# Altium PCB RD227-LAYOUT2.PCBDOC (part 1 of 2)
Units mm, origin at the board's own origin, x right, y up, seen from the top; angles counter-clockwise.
Board outline 90 x 40 mm, 4 copper layers (TOP, Mid-Layer 1, Mid-Layer 2, BOTTOM), stack 0.711 mm thick; 157 components, 70 nets, 404 pads, 437 vias.
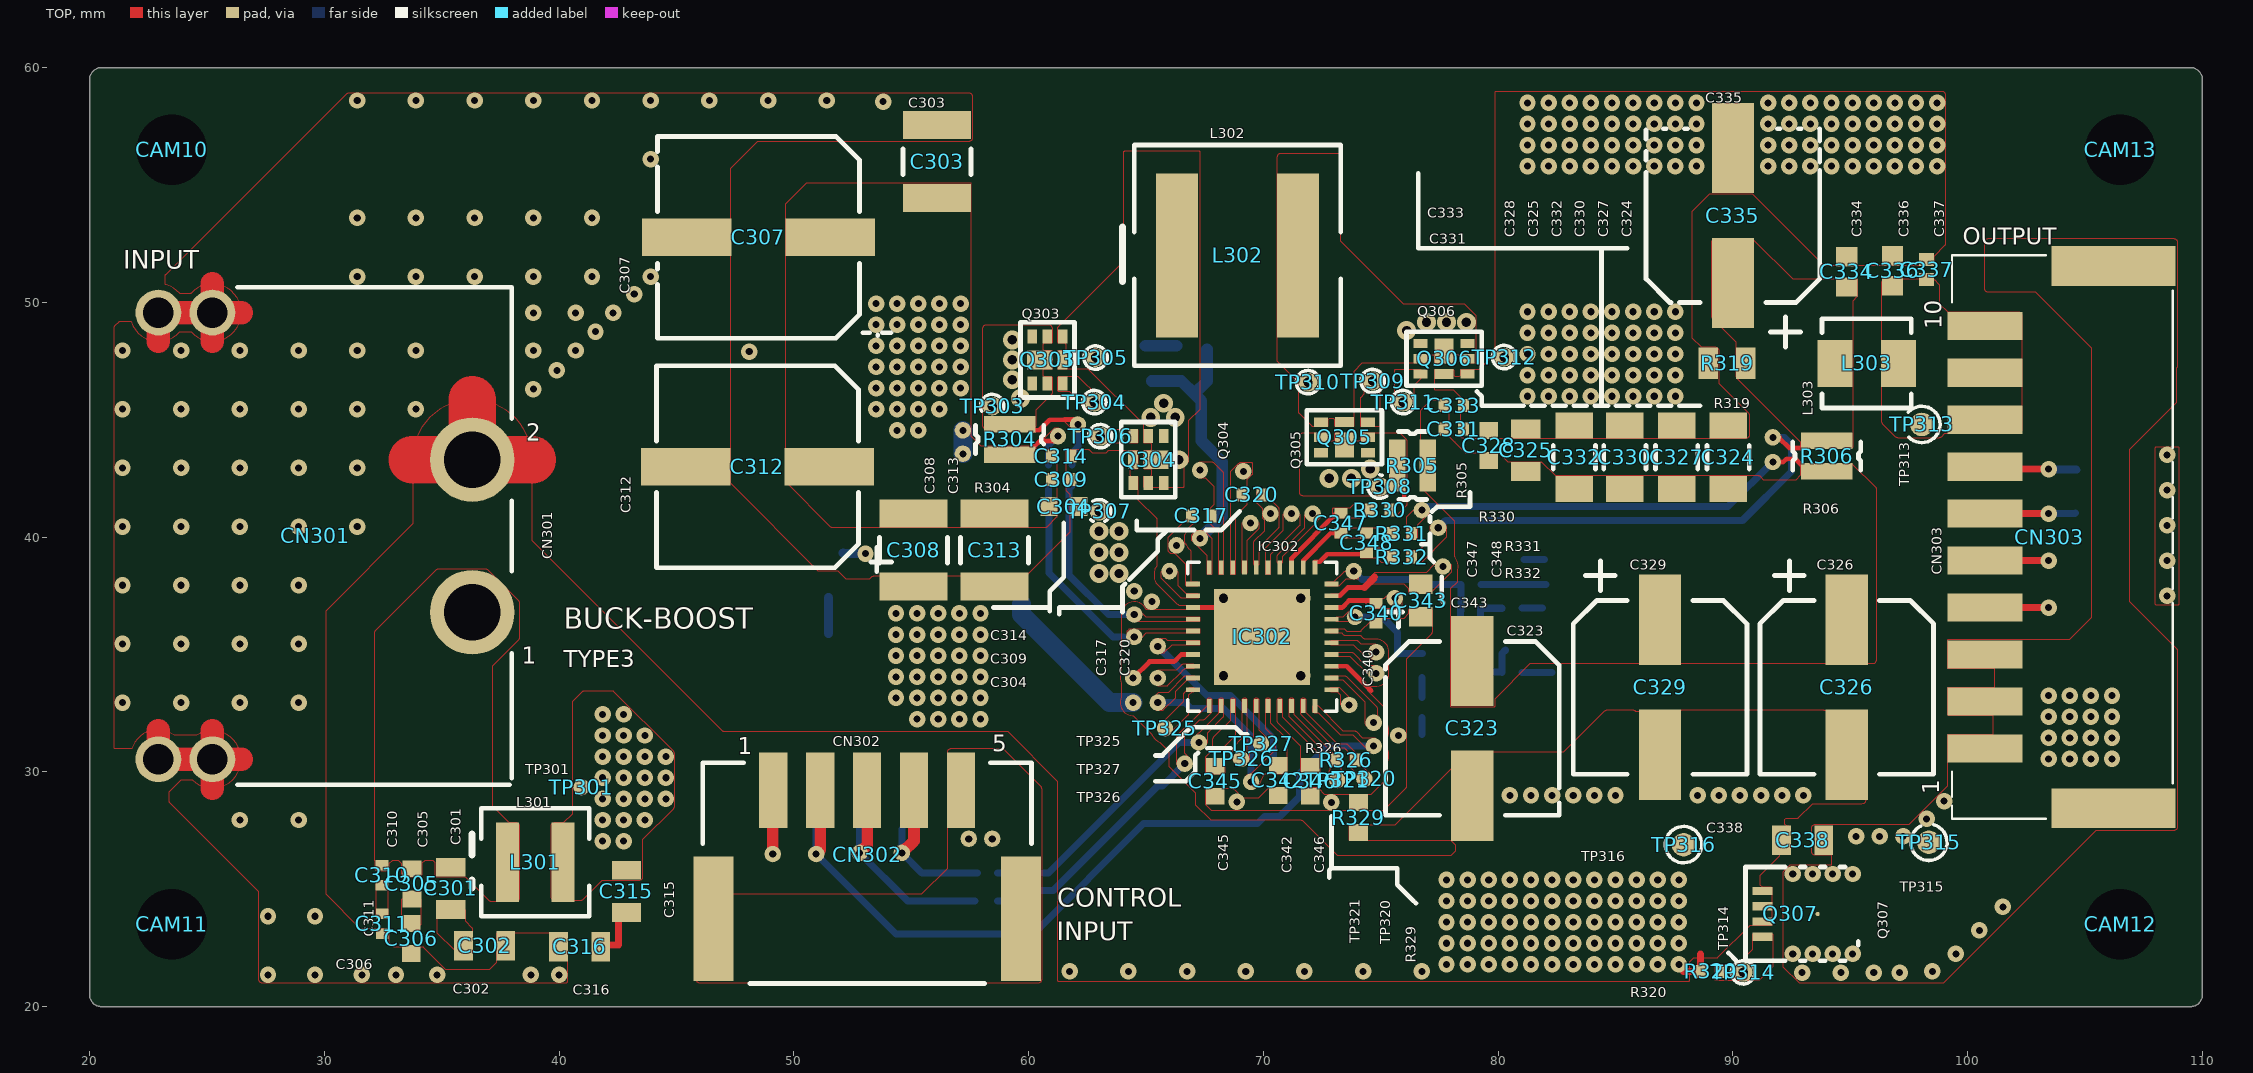
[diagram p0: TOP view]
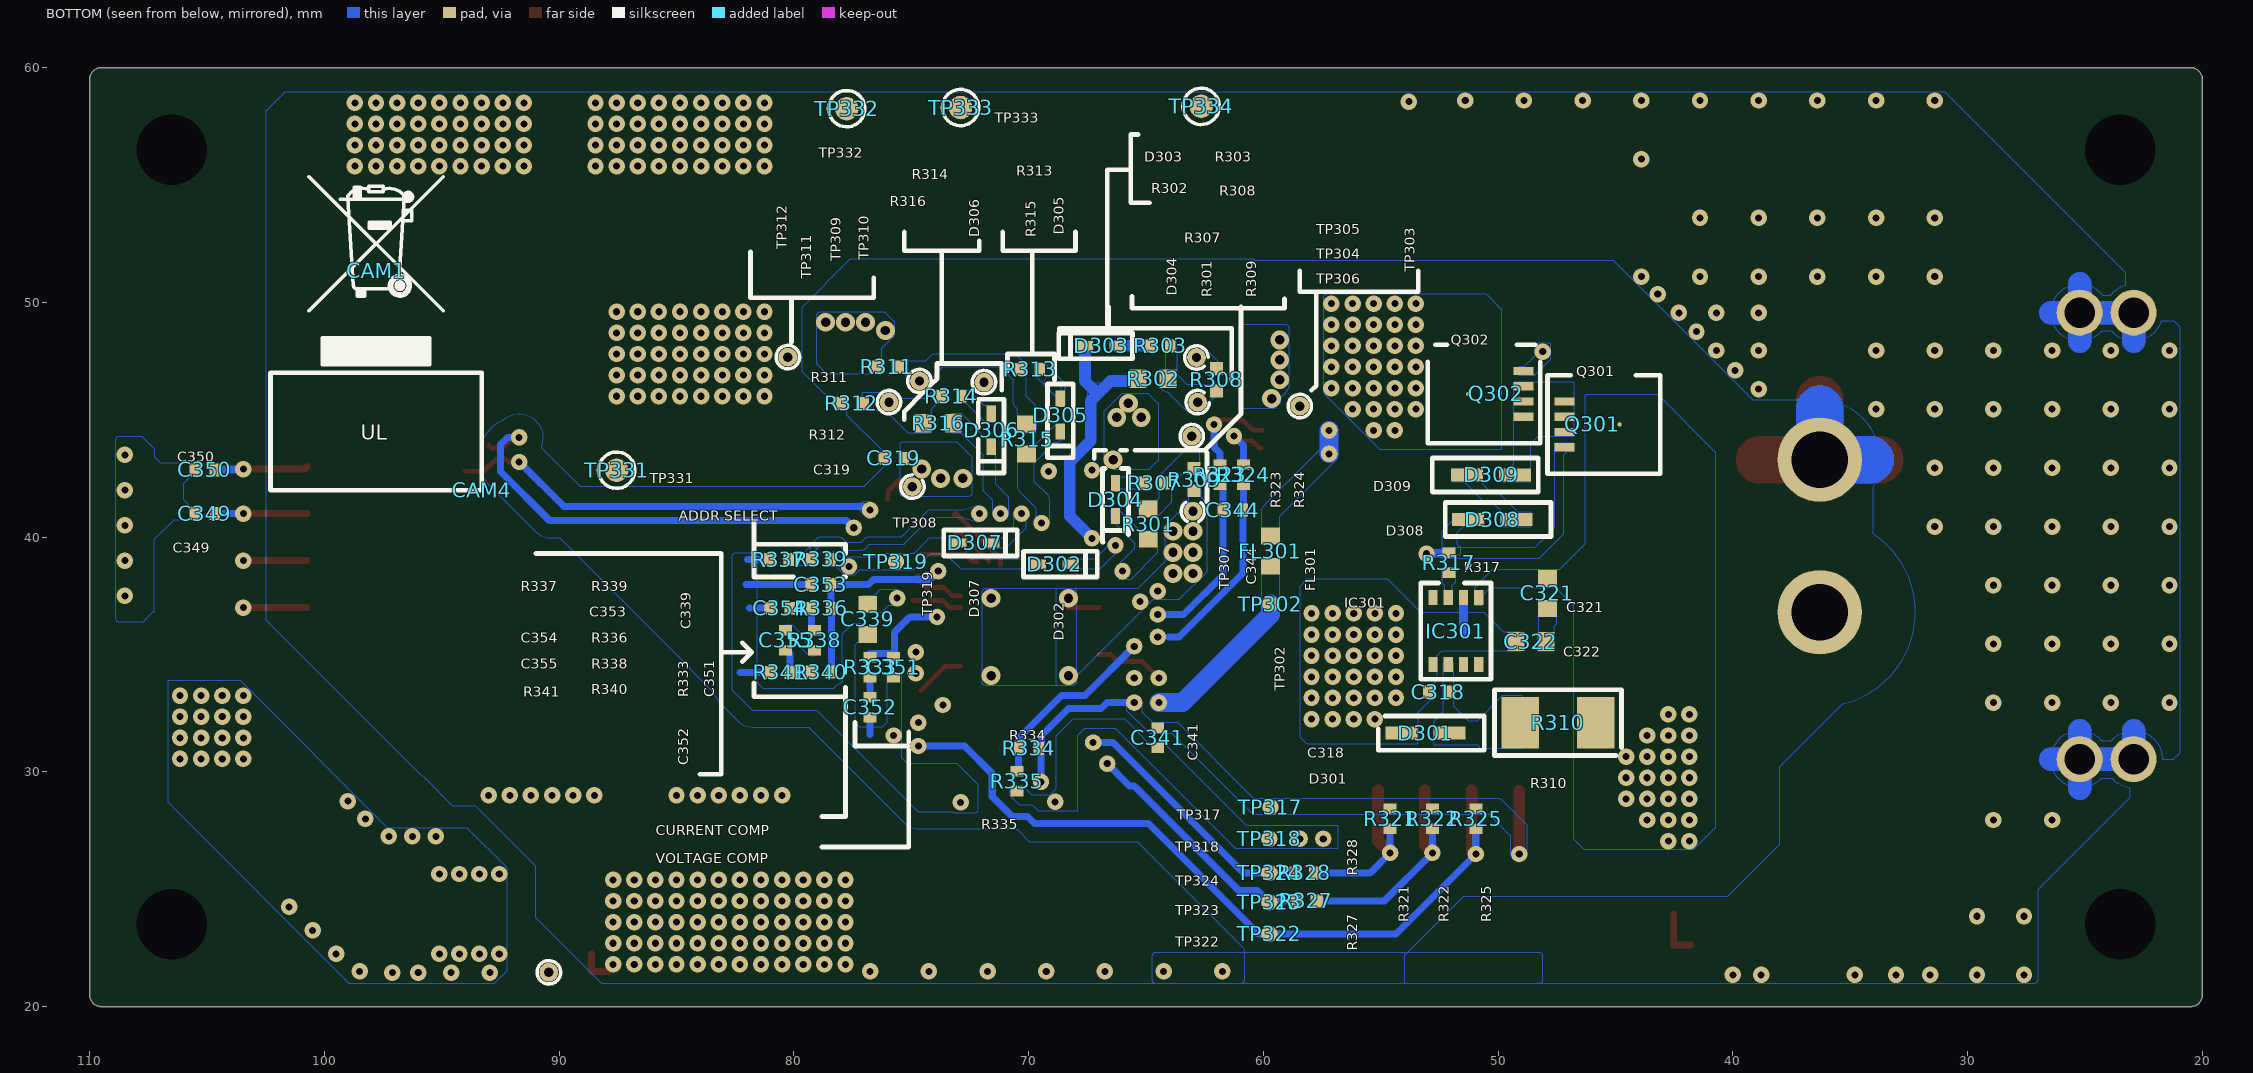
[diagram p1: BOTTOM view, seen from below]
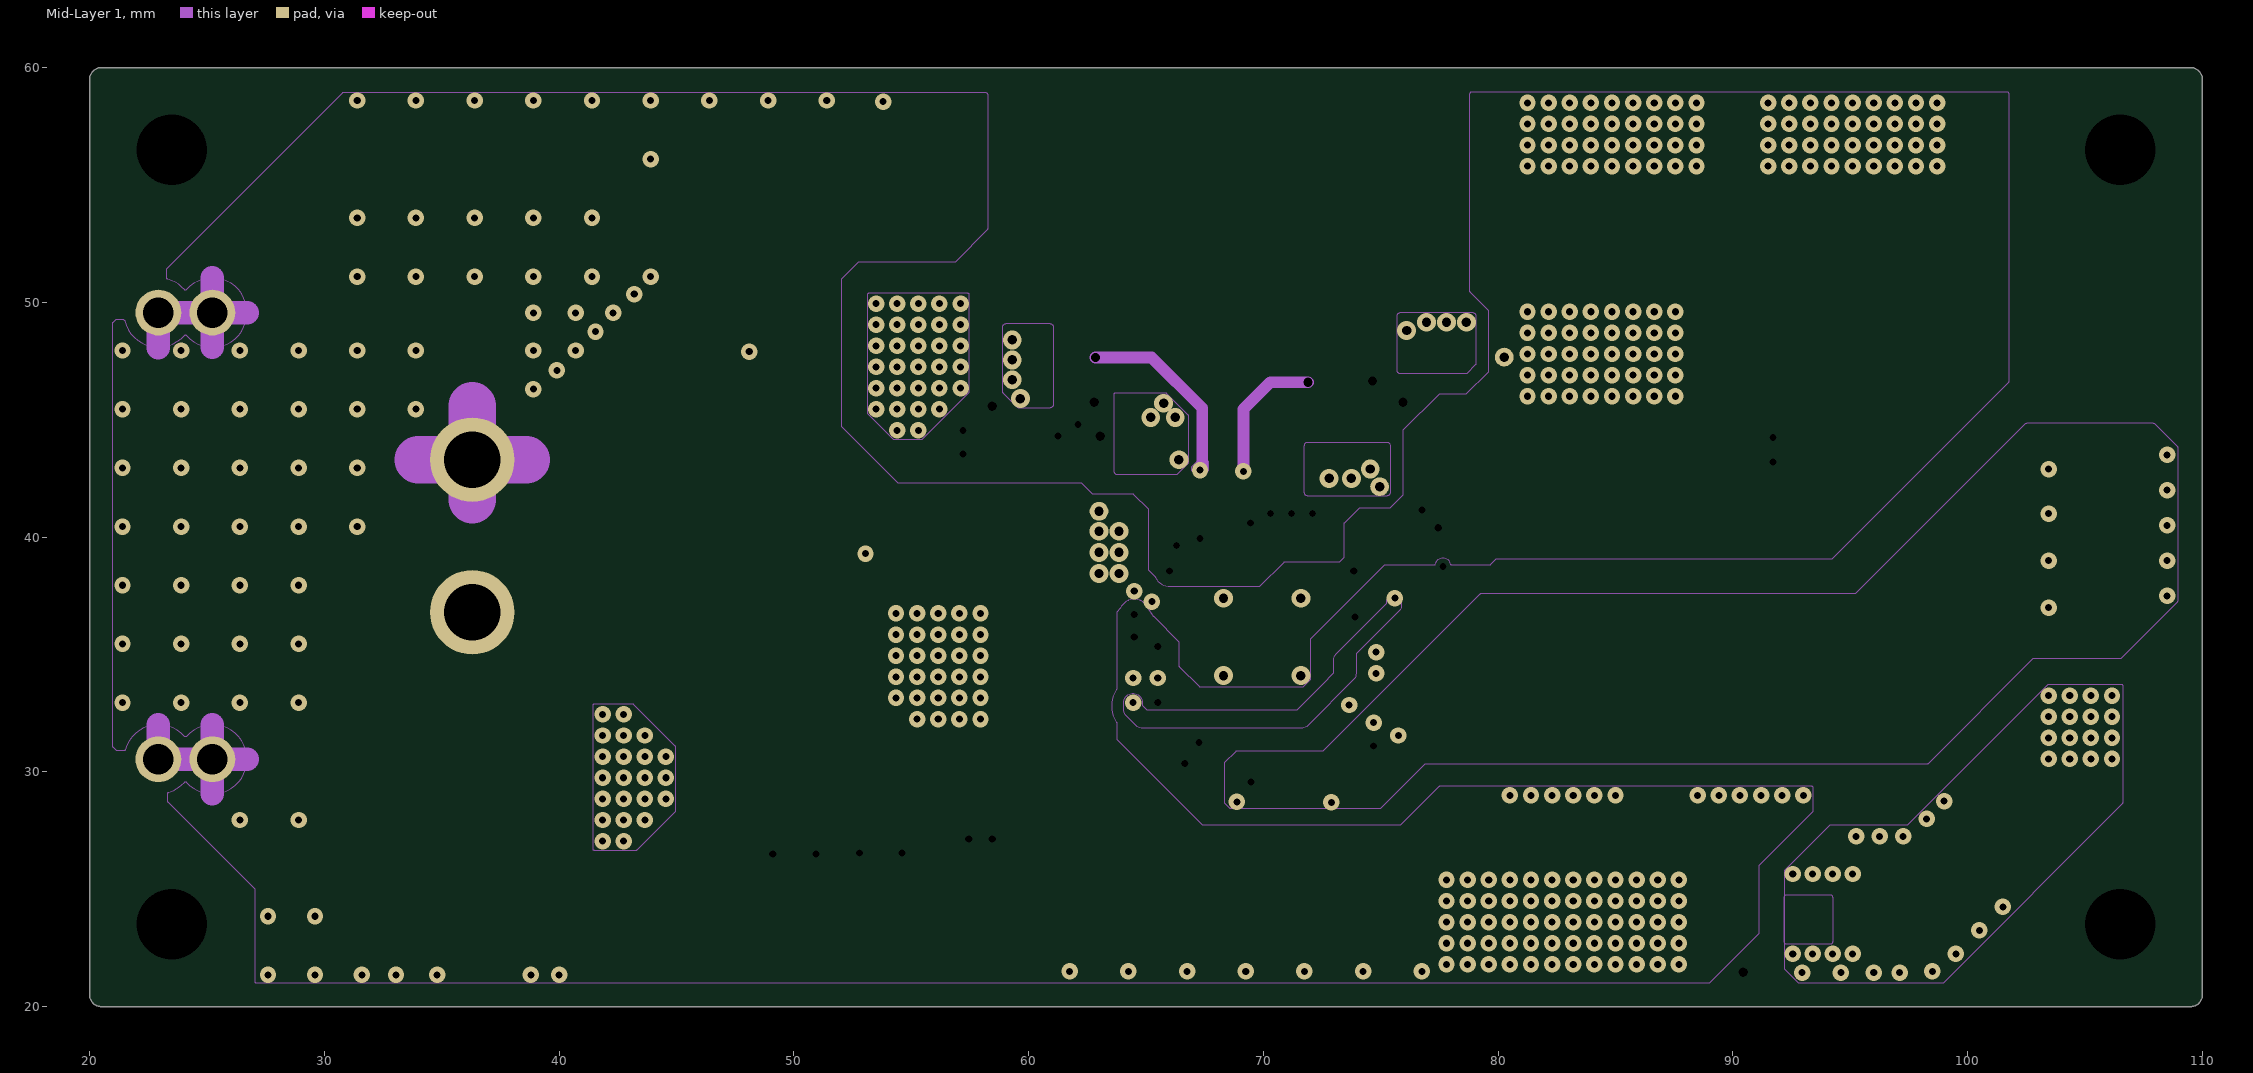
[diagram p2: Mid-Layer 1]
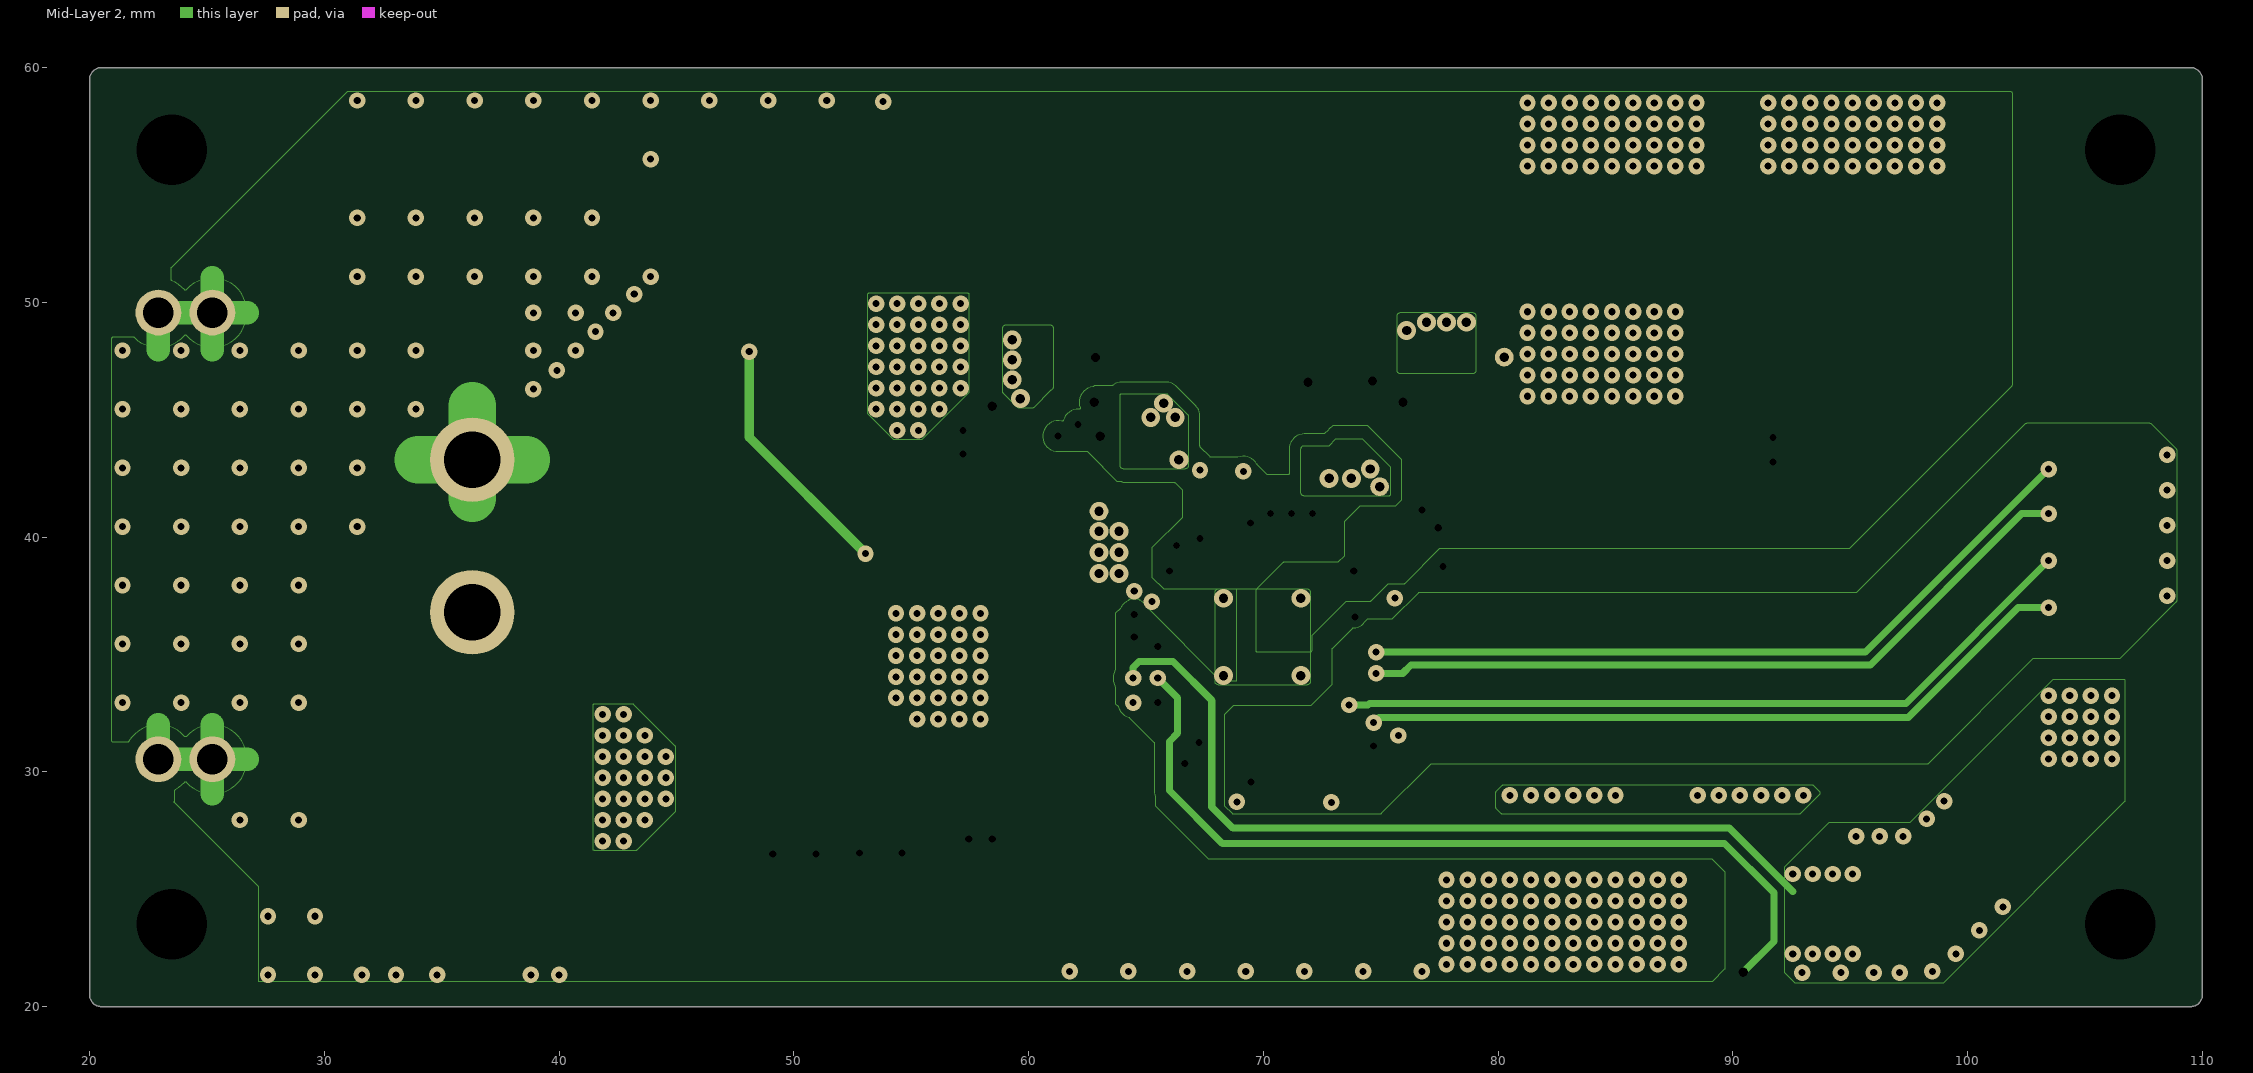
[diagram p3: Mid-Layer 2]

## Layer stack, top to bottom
Top Solder: solder mask 0.0102, Solder Resist, Dk 3.5
TOP: signal copper (thickness not stored)
Mid-Layer 1: signal copper 0.0356
Dielectric2: dielectric 0.32, FR-4, Dk 4.8
Mid-Layer 2: signal copper 0.0356
Dielectric3: dielectric 0.32, FR-4, Dk 4.8
BOTTOM: signal copper (thickness not stored)
Bottom Solder: solder mask 0.0102, Solder Resist, Dk 3.5

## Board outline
20,59.5 cw(c20.5,59.5) 20.5,60 109.5,60 cw(c109.5,59.5) 110,59.5 110,20.5 cw(c109.5,20.5) 109.5,20 20.5,20 cw(c20.5,20.5) 20,20.5

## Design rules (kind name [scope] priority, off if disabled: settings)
AssemblyTestPointUsage [All] p0: scope1count=1 scope1_0_kind=Board scope1_0_value=Board scope2count=1 scope2_0_kind=Board scope2_0_value=Board commentlength=0
AssemblyTestpoint [All] p0: scope1count=1 scope1_0_kind=Board scope1_0_value=Board scope2count=1 scope2_0_kind=Board scope2_0_value=Board commentlength=0
Clearance [All] p0: scope1count=1 scope1_0_kind=Board scope1_0_value=Board scope2count=1 scope2_0_kind=Board scope2_0_value=Board commentlength=0 gap=0.1
Clearance [All] p1: gap=0.1 ignorepadtopadclearanceinfootprint=TRUE except(0.11: SMDPad-Via; 0.15: SMDPad-SMDPad THPad-THPad Via-Via Via-Fill Via-Poly Via-Region; 0.25: SMDPad-Fill SMDPad-Poly SMDPad-Region THPad-Fill THPad-Poly THPad-Region Fill-Fill Fill-Poly Fill-Region Poly-Poly Poly-Region Region-Region; 1: Arc-Hole Track-Hole SMDPad-Hole THPad-Hole Fill-Hole Poly-Hole Region-Hole Text-Hole; 1.75: THPad-Via Via-Hole; 3: SMDPad-THPad)
ComponentClearance [All] p0: scope1count=1 scope1_0_kind=Board scope1_0_value=Board scope2count=1 scope2_0_kind=Board scope2_0_value=Board commentlength=0 gap=0.254 collisioncheckmode=3
DiffPairsRouting [All] p0: scope1count=1 scope1_0_kind=Board scope1_0_value=Board scope2count=1 scope2_0_kind=Board scope2_0_value=Board commentlength=0
FabricationTestPointUsage [All] p0: scope1count=1 scope1_0_kind=Board scope1_0_value=Board scope2count=1 scope2_0_kind=Board scope2_0_value=Board commentlength=0 valid=0 allowmultiple=FALSE
FabricationTestpoint [All] p0: scope1count=1 scope1_0_kind=Board scope1_0_value=Board scope2count=1 scope2_0_kind=Board scope2_0_value=Board commentlength=0 side=3 testpointundercomponent=TRUE minsize=1.016 maxsize=2.54 preferedsize=1.524 minholesize=0 maxholesize=1.016 preferedholesize=0.813 testpointgrid=0.025
FanoutControl Fanout_BGA [All] p0 off: scope1count=1 scope1_0_kind=Board scope1_0_value=Board scope2count=1 scope2_0_kind=Board scope2_0_value=Board commentlength=69 // Protel DXP Scope 1 Expression Was: IsBGA   Fanout_BGA (Default Rule)
FanoutControl Fanout_LCC [All] p0 off: scope1count=1 scope1_0_kind=Board scope1_0_value=Board scope2count=1 scope2_0_kind=Board scope2_0_value=Board commentlength=69 // Protel DXP Scope 1 Expression Was: IsLCC   Fanout_LCC (Default Rule)
FanoutControl Fanout_SOIC [All] p0 off: scope1count=1 scope1_0_kind=Board scope1_0_value=Board scope2count=1 scope2_0_kind=Board scope2_0_value=Board commentlength=71 // Protel DXP Scope 1 Expression Was: IsSOIC   Fanout_SOIC (Default Rule)
FanoutControl Fanout_Small [All] p0 off: scope1count=1 scope1_0_kind=Board scope1_0_value=Board scope2count=1 scope2_0_kind=Board scope2_0_value=Board commentlength=84 // Protel DXP Scope 1 Expression Was: (CompPinCount < 5)   Fanout_Small (Default Rule)
FanoutControl Fanout_Default [All] p0: scope1count=1 scope1_0_kind=Board scope1_0_value=Board scope2count=1 scope2_0_kind=Board scope2_0_value=Board commentlength=30 // Fanout_Default (Default Rule)
Height [All] p0: scope1count=1 scope1_0_kind=Board scope1_0_value=Board scope2count=1 scope2_0_kind=Board scope2_0_value=Board commentlength=0
HoleSize [All] p0: scope1count=1 scope1_0_kind=Board scope1_0_value=Board scope2count=1 scope2_0_kind=Board scope2_0_value=Board commentlength=0 absolutevalues=TRUE maxlimit=100 minlimit=0.001 maxpercent=80.000 minpercent=20.000
HoleSize [All] p1: absolutevalues=TRUE maxlimit=100 minlimit=0.001 maxpercent=80.000 minpercent=20.000
HoleToHoleClearance [All] p0: scope1count=1 scope1_0_kind=Board scope1_0_value=Board scope2count=1 scope2_0_kind=Board scope2_0_value=Board commentlength=0
HoleToHoleClearance [All] p1: gap=0.45 allowstackedmicrovias=FALSE
LayerPairs [All] p0: scope1count=1 scope1_0_kind=Board scope1_0_value=Board scope2count=1 scope2_0_kind=Board scope2_0_value=Board commentlength=0 enforce=TRUE
MinimumSolderMaskSliver [All] p0: scope1count=1 scope1_0_kind=Board scope1_0_value=Board scope2count=1 scope2_0_kind=Board scope2_0_value=Board commentlength=0
MinimumSolderMaskSliver [All] p1: minsoldermaskwidth=0.1
NetAntennae [All] p0: scope1count=1 scope1_0_kind=Board scope1_0_value=Board scope2count=1 scope2_0_kind=Board scope2_0_value=Board commentlength=0
NetAntennae [All] p1: netantennaetolerance=100
PasteMaskExpansion [All] p0: scope1count=1 scope1_0_kind=Board scope1_0_value=Board scope2count=1 scope2_0_kind=Board scope2_0_value=Board commentlength=0 expansion=0
PlaneClearance [All] p0: scope1count=1 scope1_0_kind=Board scope1_0_value=Board scope2count=1 scope2_0_kind=Board scope2_0_value=Board commentlength=0 clearance=0.001
PlaneClearance [All] p1: clearance=0.001
PlaneConnect [All] p0: scope1count=1 scope1_0_kind=Board scope1_0_value=Board scope2count=1 scope2_0_kind=Board scope2_0_value=Board commentlength=0 planeconnectstyle=Direct reliefexpansion=0.508 reliefentries=4 reliefconductorwidth=0.254 reliefairgap=0.254
PlaneConnect [All] p1: planeconnectstyle=Direct reliefexpansion=0.508 reliefentries=4 reliefconductorwidth=0.254 reliefairgap=0.254
PolygonConnect [All] p0: scope1count=1 scope1_0_kind=Board scope1_0_value=Board scope2count=1 scope2_0_kind=Board scope2_0_value=Board commentlength=0 connectstyle=Direct reliefconductorwidth=0.254 reliefentries=4 polygonreliefangle="90 Angle"
PolygonConnect [All] p1: connectstyle=Direct reliefconductorwidth=0.254 reliefentries=4 polygonreliefangle="90 Angle" airgapwidth=0.254
RoutingCorners [All] p0: scope1count=1 scope1_0_kind=Board scope1_0_value=Board scope2count=1 scope2_0_kind=Board scope2_0_value=Board commentlength=0 cornerstyle=45-Degree minsetback=2.54 maxsetback=2.54
RoutingLayers [All] p0: scope1count=1 scope1_0_kind=Board scope1_0_value=Board scope2count=1 scope2_0_kind=Board scope2_0_value=Board commentlength=0 top layer=Automatic mid layer 1=Automatic mid layer 2=Automatic bottom layer=Automatic
RoutingPriority [All] p0: scope1count=1 scope1_0_kind=Board scope1_0_value=Board scope2count=1 scope2_0_kind=Board scope2_0_value=Board commentlength=0
RoutingTopology [All] p0: scope1count=1 scope1_0_kind=Board scope1_0_value=Board scope2count=1 scope2_0_kind=Board scope2_0_value=Board commentlength=0 topology=Shortest
RoutingVias [All] p0: scope1count=1 scope1_0_kind=Board scope1_0_value=Board scope2count=1 scope2_0_kind=Board scope2_0_value=Board commentlength=0 holewidth=0.1 width=0.1 viastyle="Through Hole" minholewidth=0.001 minwidth=0.001 maxholewidth=100 maxwidth=100
RoutingVias [All] p1: holewidth=0.1 width=0.1 viastyle="Through Hole" minholewidth=0.001 minwidth=0.001 maxholewidth=100 maxwidth=100
ShortCircuit [All] p0: scope1count=1 scope1_0_kind=Board scope1_0_value=Board scope2count=1 scope2_0_kind=Board scope2_0_value=Board commentlength=0 allowed=FALSE
SilkToBoardRegionClearance [All] p0: scope1count=1 scope1_0_kind=Board scope1_0_value=Board scope2count=1 scope2_0_kind=Board scope2_0_value=Board commentlength=0
SilkToSilkClearance [All] p0: scope1count=1 scope1_0_kind=Board scope1_0_value=Board scope2count=1 scope2_0_kind=Board scope2_0_value=Board commentlength=0
SilkToSilkClearance [All] p1: silktosilkclearance=0.001
SilkToSolderMaskClearance [All] p0 off: scope1count=1 scope1_0_kind=Board scope1_0_value=Board scope2count=1 scope2_0_kind=Board scope2_0_value=Board commentlength=44 // Protel DXP Scope 1 Expression Was: IsPad
SilkToSolderMaskClearance [IsPad] p1: minsilkscreentomaskgap=0.11 clearancetoexposedcopper=TRUE
SolderMaskExpansion [All] p0: scope1count=1 scope1_0_kind=Board scope1_0_value=Board scope2count=1 scope2_0_kind=Board scope2_0_value=Board commentlength=0 expansion=0.001
SolderMaskExpansion [All] p1: expansion=0.001
UnRoutedNet [All] p0: scope1count=1 scope1_0_kind=Board scope1_0_value=Board scope2count=1 scope2_0_kind=Board scope2_0_value=Board commentlength=0
UnpouredPolygon [All] p0: scope1count=1 scope1_0_kind=Board scope1_0_value=Board scope2count=1 scope2_0_kind=Board scope2_0_value=Board commentlength=0
Width [All] p0: scope1count=1 scope1_0_kind=Board scope1_0_value=Board scope2count=1 scope2_0_kind=Board scope2_0_value=Board commentlength=0 maxlimit=1000 minlimit=2539.975 preferedwidth=0
Width [All] p1: maxlimit=1000 minlimit=2539.975 preferedwidth=0 toplayer_minwidth=0 midlayer1_minwidth=0 midlayer2_minwidth=0 bottomlayer_minwidth=0 minimp=50.000000 maximp=50.000000 favimp=50.000000
22 further rules are at their usual default settings.

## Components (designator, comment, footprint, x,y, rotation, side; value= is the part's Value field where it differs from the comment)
C301 "KC00060AKP" KC00060AKP 35.389,25.035 r90 top
C302 "KC00060AKP" KC00060AKP 36.828,22.597 r180 top
C303 "KCK03340AKP" KCK03340AKP 56.1,56 r270 top
C304 "KC00080AKP" KC00080AKP 61.5,41.3 r180 top
C305 "KC01340AKP" KC01340AKP 33.729,25.232 r90 top
C306 "KC01340AKP" KC01340AKP 33.7,22.9 r90 top
C307 "DC837K" DC837K 48.492,52.769 r0 top
C308 "KCK03340AKP" KCK03340AKP 55.1,39.45 r90 top
C309 "DC834K" DC834K 61.4,42.45 r180 top
C310 "DC834K" DC834K 32.45,25.6 r90 top
C311 "DC834K" DC834K 32.466,23.529 r90 top
C312 "DC837K" DC837K 48.45,43 r0 top
C313 "KCK03340AKP" KCK03340AKP 58.55,39.45 r90 top
C314 "DC834K" DC834K 61.4,43.45 r180 top
C315 "KC00060AKP" KC00060AKP 42.869,24.911 r90 top
C316 "KC00060AKP" KC00060AKP 40.874,22.545 r0 top
C317 "DC834K" DC834K 67.35,40.9 r0 top
C318 "DC934K" DC934K 52.55,33.4 r180 bottom
C319 "KC01540BKP01" KC01540BKP01 75.75,43.35 r0 bottom
C320 "DC834K" DC834K 69.5,41.8 r180 top
C321 "KC00080BKP" KC00080BKP 47.9,37.6 r90 bottom
C322 "KC00080BKP" KC00080BKP 48.6,35.55 r180 bottom
C323 "DC843R" DC843R 78.9,31.85 r90 top
C324 "KC00140AKP" KC00140AKP 89.8,43.4 r270 top
C325 "KC00060AKP" KC00060AKP 81.175,43.7 r270 top
C326 "DC843R" DC843R 94.85,33.6 r90 top
C327 "KC00140AKP" KC00140AKP 87.6,43.4 r270 top
C328 "KC00080AKP" KC00080AKP 79.6,43.9 r270 top
C329 "DC843R" DC843R 86.9,33.6 r90 top
C330 "KC00140AKP" KC00140AKP 85.4,43.4 r270 top
C331 "DC834K" DC834K 78.1,44.6 r180 top
C332 "KC00140AKP" KC00140AKP 83.25,43.4 r270 top
C333 "DC834K" DC834K 78.1,45.6 r180 top
C334 "KCK02380AKP01" KCK02380AKP01 94.85,51.3 r270 top
C335 "DC843R" DC843R 90,53.7 r270 top
C336 "KCK02380AKP01" KCK02380AKP01 96.8,51.35 r270 top
C337 "KC01540AKP" KC01540AKP 98.25,51.4 r270 top
C338 "KC00060AKP" KC00060AKP 92.966,27.09 r0 top
C339 "KC00080BKP" KC00080BKP 76.85,36.5 r90 bottom
C340 "DC834K" DC834K 74.8,36.75 r90 top
C341 "DC934K" DC934K 64.5,31.45 r90 bottom
C342 "KC01670AKP" KC01670AKP 70.631,29.633 r270 top
C343 "KC01560AKP" KC01560AKP 76.7,37.3 r270 top
C344 "DC934K" DC934K 61.3,41.15 r0 bottom
C345 "KC00080AKP" KC00080AKP 67.95,29.6 r270 top
C346 "KC00080AKP" KC00080AKP 72,29.6 r270 top
C347 "DC834K" DC834K 73.3,40.6 r90 top
C348 "DC834K" DC834K 74.4,39.75 r90 top
C349 "DC934K" DC934K 105.1,41 r180 bottom
C350 "DC934K" DC934K 105.092,42.864 r180 bottom
C351 "DC934K" DC934K 75.75,34.45 r90 bottom
C352 "DC934K" DC934K 76.75,32.75 r90 bottom
C353 "DC934K" DC934K 78.845,37.981 r180 bottom
C354 "DC934K" DC934K 80.599,36.972 r180 bottom
C355 "DC934K" DC934K 80.35,35.6 r90 bottom
CAM1 "CAM_LOGO_MARK_WEEE-B" CAM_LOGO_MARK_WEEE-B 97.8,51.35 r0 bottom
CAM4 "Local_ULCMN-B" Local_ULCMN-B 93.3,42 r0 bottom
CAM10 "NTC300" NTC300 23.5,56.5 r0 top
CAM11 "NTC300" NTC300 23.5,23.5 r0 top
CAM12 "NTC300" NTC300 106.5,23.5 r0 top
CAM13 "NTC300" NTC300 106.5,56.5 r0 top
CN301 "Local_HVH-280-2P-6_5DS" Local_HVH-280-2P-6_5DS 36.3,36.8 r270 top
CN302 "Local_502352-0501" Local_502352-0501 53.121,25.687 r0 top
CN303 "Local_502352-1000" Local_502352-1000 104,40 r90 top
D301 "D9K022" D9K022 53.1,31.65 r0 bottom
D302 "D8101D1BKP" D8101D1BKP 68.9,38.85 r0 bottom
D303 "D8101D1BKP" D8101D1BKP 66.9,48.15 r180 bottom
D304 "D8101D1BKP" D8101D1BKP 66.3,41.6 r90 bottom
D305 "D8101D1BKP" D8101D1BKP 68.65,45.2 r90 bottom
D306 "D8101D1BKP" D8101D1BKP 71.6,44.55 r90 bottom
D307 "D8101D1BKP" D8101D1BKP 72.3,39.75 r0 bottom
D308 "D9K022" D9K022 50.25,40.75 r0 bottom
D309 "D9K022" D9K022 50.3,42.65 r180 bottom
FL301 "KC00080BKP" KC00080BKP 59.7,39.4 r270 bottom
IC301 "SN00281BKP" SN00281BKP 51.8,36 r180 bottom
IC302 "Local_MAX25432BATLGV+-A" Local_MAX25432BATLGV+-A 69.95,35.75 r0 top
L301 "Local_XEL-4030-471MEC" Local_XEL-4030-471MEC 38.984,26.149 r0 top
L302 "Local_XAL8080-103MED" Local_XAL8080-103MED 68.9,52 r0 top
L303 "Local_IHLP1212BZEVR22M5A" Local_IHLP1212BZEVR22M5A 95.7,47.4 r0 top
Q301 "SN00612BKP" SN00612BKP 45.5,44.8 r90 bottom
Q302 "SN00612BKP" SN00612BKP 50.6,46.1 r270 bottom
Q303 "SNP10011AKP" SNP10011AKP 60.8,47.55 r0 top
Q304 "SNP10011AKP" SNP10011AKP 65.1,43.3 r180 top
Q305 "SNP10011AKP" SNP10011AKP 73.45,44.25 r90 top
Q306 "SNP10011AKP" SNP10011AKP 77.7,47.6 r270 top
Q307 "SN00612AKP" SN00612AKP 92.935,23.948 r270 top
R301 "KC00080BKP" KC00080BKP 64.9,40.55 r270 bottom
R302 "KC00080BKP" KC00080BKP 64.7,46.75 r0 bottom
R303 "DC934K" DC934K 64.4,48.15 r0 bottom
R304 "Local_KRL2012" Local_KRL2012 59.19,44.166 r90 top
R305 "Local_KRL2012" Local_KRL2012 76.35,43.05 r0 top
R306 "Local_KRL2012" Local_KRL2012 94,43.45 r90 top
R307 "DC934K" DC934K 64.65,42.3 r0 bottom
R308 "KC01310BKP" KC01310BKP 62,46.7 r270 bottom
R309 "KC01310BKP" KC01310BKP 62.95,42.45 r90 bottom
R310 "DR901RF" DR901RF 47.45,32.1 r180 bottom
R311 "KC01310BKP" KC01310BKP 76.05,47.25 r180 bottom
R312 "KC01310BKP" KC01310BKP 77.55,45.7 r180 bottom
R313 "DC934K" DC934K 69.95,47.15 r180 bottom
R314 "DC934K" DC934K 73.3,46 r180 bottom
R315 "KC00080BKP" KC00080BKP 70.09,44.175 r270 bottom
R316 "KC00080BKP" KC00080BKP 73.85,44.85 r180 bottom
R317 "DR924K" DR924K 52.1,38.9 r90 bottom
R319 "DR810K" DR810K 89.75,47.4 r0 top
R320 "DR824K" DR824K 89.051,21.503 r0 top
R321 "DR924K" DR924K 54.6,28 r270 bottom
R322 "DR924K" DR924K 52.8,28 r270 bottom
R323 "DC934K" DC934K 61.85,42.65 r90 bottom
R324 "DC934K" DC934K 60.85,42.65 r90 bottom
R325 "DR924K" DR924K 50.95,28 r270 bottom
R326 "DR824K" DR824K 73.5,30.5 r180 top
R327 "KC01310BKP" KC01310BKP 58.2,24.5 r180 bottom
R328 "DR924K" DR924K 58.25,25.7 r180 bottom
R329 "KC00080AKP" KC00080AKP 74.05,28.05 r90 top
R330 "DR824K" DR824K 74.95,41.15 r180 top
R331 "DR824K" DR824K 75.9,40.15 r180 top
R332 "DR824K" DR824K 75.9,39.15 r180 top
R333 "DR924K" DR924K 76.75,34.45 r90 bottom
R334 "DR924K" DR924K 70,31 r0 bottom
R335 "DR924K" DR924K 70.5,29.6 r270 bottom
R336 "KC00050BKP" KC00050BKP 78.829,36.97 r180 bottom
R337 "DR924K" DR924K 80.635,39.039 r0 bottom
R338 "DR924K" DR924K 79.113,35.602 r90 bottom
R339 "DR924K" DR924K 78.85,39.05 r0 bottom
R340 "DR924K" DR924K 78.85,34.251 r180 bottom
R341 "DR924K" DR924K 80.592,34.24 r180 bottom
TP301 "TL0.7_A_noMM" TL0.7_A_noMM 40.95,29.35 r0 top
TP302 "TL0.7_B_noMM" TL0.7_B_noMM 59.7,37.15 r0 bottom
TP303 "Local_TL0.4_TH-A" Local_TL0.4_TH-A#1 58.45,45.583 r0 top
TP304 "Local_TL0.4_TH-A" Local_TL0.4_TH-A#1 62.8,45.75 r0 top
TP305 "Local_TL0.4_TH-A" Local_TL0.4_TH-A#1 62.85,47.65 r0 top
TP306 "Local_TL0.4_TH-A" Local_TL0.4_TH-A#1 63.05,44.3 r0 top
TP307 "Local_TL0.4_TH-A" Local_TL0.4_TH-A#2 63,41.1 r0 top
TP308 "Local_TL0.4_TH-A" Local_TL0.4_TH-A#2 74.95,42.15 r0 top
TP309 "Local_TL0.4_TH-A" Local_TL0.4_TH-A#1 74.65,46.65 r0 top
TP310 "Local_TL0.4_TH-A" Local_TL0.4_TH-A#1 71.9,46.6 r0 top
TP311 "Local_TL0.4_TH-A" Local_TL0.4_TH-A#1 75.95,45.75 r0 top
TP312 "Local_TL0.4_TH-A" Local_TL0.4_TH-A#2 80.258,47.67 r0 top
TP313 "Local_TP-100-A" Local_TP-100-A 98.05,44.8 r0 top
TP314 "Local_TL0.4_TH-A" Local_TL0.4_TH-A#1 90.437,21.463 r0 top
TP315 "Local_TP-100-A" Local_TP-100-A 98.35,27 r0 top
TP316 "Local_TP-100-A" Local_TP-100-A 87.9,26.9 r0 top
TP317 "TL0.7_B_noMM" TL0.7_B_noMM 59.7,28.5 r0 bottom
TP318 "TL0.7_B_noMM" TL0.7_B_noMM 59.75,27.15 r0 bottom
TP319 "TL0.7_B_noMM" TL0.7_B_noMM 75.65,38.95 r0 bottom
TP320 "TL0.7_A_noMM" TL0.7_A_noMM 74.3,29.7 r0 top
TP321 "TL0.7_A_noMM" TL0.7_A_noMM 73.15,29.65 r0 top
TP322 "TL0.7_B_noMM" TL0.7_B_noMM 59.75,23.1 r0 bottom
TP323 "TL0.7_B_noMM" TL0.7_B_noMM 59.75,24.45 r0 bottom
TP324 "TL0.7_B_noMM" TL0.7_B_noMM 59.75,25.7 r0 bottom
TP325 "TL0.7_A_noMM" TL0.7_A_noMM 65.808,31.864 r0 top
TP326 "TL0.7_A_noMM" TL0.7_A_noMM 69.05,30.55 r0 top
TP327 "TL0.7_A_noMM" TL0.7_A_noMM 69.9,31.2 r0 top
TP331 "Local_TP-100-B" Local_TP-100-B 87.55,42.85 r0 bottom
TP332 "Local_TP-100-B" Local_TP-100-B 77.75,58.25 r0 bottom
TP333 "Local_TP-100-B" Local_TP-100-B 72.9,58.3 r0 bottom
TP334 "Local_TP-100-B" Local_TP-100-B 62.65,58.35 r0 bottom

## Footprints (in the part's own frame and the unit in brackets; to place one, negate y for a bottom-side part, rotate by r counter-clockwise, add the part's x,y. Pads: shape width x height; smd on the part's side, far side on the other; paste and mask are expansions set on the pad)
CAM_LOGO_MARK_WEEE-B [mm] "KC00080BKP"
  silkscreen extent -2.86,-4 2.86,4
D9K022 [mm] "KC00080BKP"
  rect 1.36x0.55 smd paste-1.36 mask+0: A(1.025,0) C(-1.025,0)
  silkscreen extent -2.51,-0.72 2,0.72
D8101D1BKP [mm] "KC00080BKP"
  rect 0.7x0.4 smd paste-0.7 mask+0: A(0.7,0) C(-0.7,0)
  silkscreen extent -1.82,-0.55 1.32,0.55
DC834K [mm] "KC00080BKP"
  rect 0.45x0.55 smd paste-0.55 mask+0: 1(-0.425,0) 2(0.425,0)
DC837K [mm] "KC00080BKP"
  rect 3.82x1.6 smd paste-3.82 mask+0: 1(-3.06,0) 2(3.06,0)
  silkscreen extent -4.3,-4.3 5.64,4.3
DC843R [mm] "KC00080BKP"
  rect 3.85x1.8 smd paste-3.85 mask+0: 1(-2.875,0) 2(2.875,0)
  silkscreen extent -3.7,-3.7 5.14,3.7
DC934K [mm] "KC00080BKP"
  rect 0.45x0.55 smd paste-0.55 mask+0: 1(-0.425,0) 2(0.425,0)
DR810K [mm] "KC00080BKP"
  rect 0.83x1.35 smd paste-1.35 mask+0: 1(-0.8,0) 2(0.8,0)
DR824K [mm] "KC00080BKP"
  rect 0.45x0.55 smd paste-0.55 mask+0: 1(-0.425,0) 2(0.425,0)
DR901RF [mm] "KC00080BKP"
  rect 1.6x2.2 smd paste-2.2 mask+0: 1(-1.6,0) 2(1.6,0)
  silkscreen extent -2.7,-1.4 2.7,1.4
DR924K [mm] "KC00080BKP"
  rect 0.45x0.55 smd paste-0.55 mask+0: 1(-0.425,0) 2(0.425,0)
KC00050BKP [mm] "KC00080BKP"
  rect 0.45x0.55 smd paste-0.55 mask+0: 1(-0.425,0) 2(0.425,0)
KC00060AKP [mm] "KC00080BKP"
  rect 0.8x1.25 smd paste-1.25 mask+0: 1(-0.9,0) 2(0.9,0)
KC00080AKP [mm] "KC00080BKP"
  rect 0.72x0.8 smd paste-0.8 mask+0: 1(-0.64,0) 2(0.64,0)
KC00080BKP [mm] "KC00080BKP"
  rect 0.72x0.8 smd paste-0.8 mask+0: 1(-0.64,0) 2(0.64,0)
KC00140AKP [mm] "KC00080BKP"
  rect 1.1x1.6 smd paste-1.6 mask+0: 1(-1.35,0) 2(1.35,0)
  silkscreen extent -0.5,-0.9 0.5,0.9
KC01310BKP [mm] "KC00080BKP"
  rect 0.55x0.55 smd paste-0.55 mask+0: 1(-0.475,0) 2(0.475,0)
KC01340AKP [mm] "KC00080BKP"
  rect 0.72x0.8 smd paste-0.8 mask+0: 1(-0.64,0) 2(0.64,0)
KC01540AKP [mm] "KC00080BKP"
  rect 0.55x0.65 smd paste-0.65 mask+0: 1(-0.425,0) 2(0.425,0)
KC01540BKP01 [mm] "KC00080BKP"
  rect 0.45x0.55 smd paste-0.55 mask+0: 1(-0.425,0) 2(0.425,0)
KC01560AKP [mm] "KC00080BKP"
  rect 0.83x1 smd paste-1 mask+0: 1(-0.695,0) 2(0.695,0)
KC01670AKP [mm] "KC00080BKP"
  rect 0.72x0.8 smd paste-0.8 mask+0: 1(-0.64,0) 2(0.64,0)
KCK02380AKP01 [mm] "KC00080BKP"
  rect 0.82x0.9 smd paste-0.9 mask+0: 1(-0.64,0) 2(0.64,0)
KCK03340AKP [mm] "KC00080BKP"
  rect 1.2x2.9 smd paste-2.9 mask+0: 1(-1.55,0) 2(1.55,0)
  silkscreen extent -0.55,-1.45 0.55,1.45
Local_502352-0501 [mm] "KC00080BKP"
  rect 1.2x3.2 smd paste-3.2 mask+0: 1(-4,3.53) 2(-2,3.53) 3(0,3.53) 4(2,3.53) 5(4,3.53)
  rect 1.7x5.3 smd paste-5.3 mask+0: 1T(-6.55,-1.95) 2T(6.55,-1.95)
  silkscreen extent -7,-4.7 7,4.7
Local_502352-1000 [mm] "KC00080BKP"
  rect 1.2x3.2 smd paste-3.2 mask+0: 1(-9,3.265) 2(-7,3.265) 3(-5,3.265) 4(-3,3.265) 5(-1,3.265) 6(1,3.265) 7(3,3.265) 8(5,3.265) 9(7,3.265) 10(9,3.265)
  rect 1.7x5.3 smd paste-5.3 mask+0: 1T(-11.55,-2.215) 2T(11.55,-2.215)
  silkscreen extent -12,-4.73 12,4.66
Local_HVH-280-2P-6_5DS [mm] "KC00080BKP"
  round 3.6 hole 2.4 paste-3.6 mask+0: 1(0,0) 2(-6.5,0)
  round 1.95 hole 1.3 paste-1.95 mask+0: 1T(6.265,-13.37) 2T(6.265,-11.07) 3T(-12.765,-11.07) 4T(-12.765,-13.37)
  silkscreen extent -13.85,-10 7.35,1.68
Local_IHLP1212BZEVR22M5A [mm] "KC00080BKP"
  rect 1.5x2 smd paste-2 mask+0: 1(-1.35,0) 2(1.35,0)
  silkscreen extent -1.9,-1.9 1.9,1.9
Local_KRL2012 [mm] "KC00080BKP"
  rect 0.7x2.2 smd paste-2.2 mask+0: 1(-0.65,0) 2(0.65,0)
  silkscreen extent -0.6,-1.45 0.6,1.45
Local_MAX25432BATLGV+-A [mm] "KC00080BKP"
  rect 0.6x0.2 smd paste-0.6 mask+0: 1(-2.948,2.25) 2(-2.948,1.75) 3(-2.948,1.25) 4(-2.948,0.75) 5(-2.948,0.25) 6(-2.948,-0.25) 7(-2.948,-0.75) 8(-2.948,-1.25) 9(-2.948,-1.75) 10(-2.948,-2.25) 21(2.948,-2.25) 22(2.948,-1.75) 23(2.948,-1.25) 24(2.948,-0.75) 25(2.948,-0.25) 26(2.948,0.25) 27(2.948,0.75) 28(2.948,1.25) 29(2.948,1.75) 30(2.948,2.25)
  rect 0.2x0.6 smd paste-0.6 mask+0: 11(-2.25,-2.948) 12(-1.75,-2.948) 13(-1.25,-2.948) 14(-0.75,-2.948) 15(-0.25,-2.948) 16(0.25,-2.948) 17(0.75,-2.948) 18(1.25,-2.948) 19(1.75,-2.948) 20(2.25,-2.948) 31(2.25,2.948) 32(1.75,2.948) 33(1.25,2.948) 34(0.75,2.948) 35(0.25,2.948) 36(-0.25,2.948) 37(-0.75,2.948) 38(-1.25,2.948) 39(-1.75,2.948) 40(-2.25,2.948)
  rect 4.089x4.089 smd paste-4.089 mask+0: 41(0,0)
  silkscreen extent -3.17,-3.17 3.17,3.17
Local_TL0.4_TH-A#1 [mm] "KC00080BKP"
  round 0.8 / inner round 0 / far side round 0.8 hole 0.4 paste-0.8 mask+0: 1(0,0)
  silkscreen extent -0.5,-0.21 0.5,0.5
Local_TL0.4_TH-A#2 [mm] "KC00080BKP"
  round 0.8 hole 0.4 paste-0.8 mask+0: 1(0,0)
  silkscreen extent -0.35,-0.43 0.5,0.5
Local_TP-100-A [mm] "KC00080BKP"
  round 1 smd paste-1 mask+0: 1(0,0)
  silkscreen extent -0.58,-0.77 0.77,0.77
Local_TP-100-B [mm] "KC00080BKP"
  round 1 smd paste-1 mask+0: 1(0,0)
  silkscreen extent -0.77,-0.77 0.77,0.77
Local_ULCMN-B [mm] "KC00080BKP"
  silkscreen extent 0,-5 9,0
Local_XAL8080-103MED [mm] "KC00080BKP"
  rect 1.78x7 smd paste-7 mask+0: 1(-2.58,0) 2(2.58,0)
  silkscreen extent -4.9,-4.7 4.4,4.7
Local_XEL-4030-471MEC [mm] "KC00080BKP"
  rect 0.98x3.4 smd paste-3.4 mask+0: 1(-1.185,0) 2(1.185,0)
  silkscreen extent -2.7,-2.3 2.3,2.3
NTC300 [mm] "KC00080BKP"
  round 0 hole 3 unplated paste-3.5 mask+0: ""(0,0)
SN00281BKP [mm] "KC00080BKP"
  rect 0.4x0.65 smd paste-0.65 mask+0: 1(0.975,1.425) 2(0.325,1.425) 3(-0.325,1.425) 4(-0.975,1.425) 5(-0.975,-1.425) 6(-0.325,-1.425) 7(0.325,-1.425) 8(0.975,-1.425)
  silkscreen extent -1.5,-2.05 1.5,2.05
SN00612AKP [mm] "KC00080BKP"
  rect 0.35x0.85 smd paste-0.85 mask+0: 1(-0.975,-1.675) 2(-0.325,-1.675) 3(0.325,-1.675) 4(0.975,-1.675)
  round 0.178 smd paste-0.178 mask+0: 5(0,0.675)
  silkscreen extent -2,-2.4 2,2.4
SN00612BKP [mm] "KC00080BKP"
  rect 0.35x0.85 smd paste-0.85 mask+0: 1(0.975,1.675) 2(0.325,1.675) 3(-0.325,1.675) 4(-0.975,1.675)
  round 0.178 smd paste-0.178 mask+0: 5(0,-0.675)
  silkscreen extent -2.1,-2.4 2.1,2.4
SNP10011AKP [mm] "KC00080BKP"
  rect 0.4x0.6 smd paste-0.6 mask+0: 1(-0.65,-1) 2(0,-1) 3(0.65,-1) 4(0.65,1) 5(0,1) 6(-0.65,1)
  rect 1.075x0.8 smd paste-1.075 mask+0: 7(-0.325,0)
  rect 0.425x0.8 smd paste-0.8 mask+0: 8(0.65,0)
  silkscreen extent -1.15,-1.6 1.15,1.6
TL0.7_A_noMM [mm] "KC00080BKP"
  round 0.7 smd paste-0.8 mask+0: 1(0,0)
TL0.7_B_noMM [mm] "KC00080BKP"
  round 0.7 smd paste-0.8 mask+0: 1(0,0)

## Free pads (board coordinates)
  round 0.7 / inner round 0 / far side round 0.7 hole 0.3 paste-0.7 mask+0: ""(49.1,26.5) ""(50.95,26.5) ""(52.8,26.55) ""(54.6,26.55) ""(57.2,43.55) ""(57.2,44.55) ""(57.45,27.15) ""(58.45,27.15) ""(61.25,44.3) ""(62.1,44.8) ""(64.5,35.75) ""(64.5,36.7) ""(65.5,32.95) ""(65.5,35.35) ""(66,38.55) ""(66.3,39.65) ""(66.65,30.35) ""(67.25,31.25) ""(67.3,39.95) ""(69.45,40.6) ""(69.475,29.575) ""(70.3,41) ""(71.2,41) ""(72.1,41) ""(73.85,38.55) ""(73.9,36.6) ""(74.7,31.1) ""(76.75,41.15) ""(77.45,40.4) ""(77.65,38.75) ""(91.7,43.2) ""(91.7,44.25)

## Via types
v1: diameter 0.7, hole 0.3, TOP to BOTTOM, 412 vias
v2: diameter 0.8, hole 0.4, TOP to BOTTOM, 25 vias

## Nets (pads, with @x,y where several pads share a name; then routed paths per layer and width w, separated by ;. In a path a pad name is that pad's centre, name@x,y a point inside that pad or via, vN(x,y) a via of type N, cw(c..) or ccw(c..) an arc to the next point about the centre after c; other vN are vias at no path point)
ADDR: IC302.34 pad.@72.1,41 R337.1 R339.2
ALERT: CN302.2 IC302.20 pad.@50.95,26.5 pad.@74.7,31.1 R325.2 TP322.1 | length 32.9
  TOP w0.5: pad.@50.95,26.5 51.121,26.671 CN302.2@51.121,29.217
  BOTTOM w0.3: R325.2@50.95,27.575 pad.@50.95,26.5 54.35,23.1 TP322.1@59.75,23.1 60.2,23.1 64.9,27.8 69.75,27.8 70.05,28.1 70.7,28.1 71.55,28.95 71.55,29.921 72.729,31.1 pad.@74.7,31.1
BIAS: C343.1 D302.A D307.A IC302.29 pad.@77.65,38.75 R339.1 TP319.1 | length 2.2
  TOP w0.2: IC302.29@72.898,37.5 73.25,37.5 73.6,37.85 74.3,37.85
  TOP w0.3: 74.3,37.85 74.743,38.293
BST1: C317.1 D302.C IC302.1 pad.@66.3,39.65
BST2: C320.1 D307.C IC302.36 pad.@70.3,41
CSN1: pad.@62.1,44.8 Q303.1 Q303.2 Q303.5 Q303.6 Q303.7 R304.2 R323.2 TP303.1 | length 4.1
  TOP w0.2: R304.2@60.05,44.55 60.45,44.55 60.9,45 61.9,45 pad.@62.1,44.8
  BOTTOM w0.3: R323.2@61.85,43.075 61.85,43.58 62.1,43.83 pad.@62.1,44.8
  other v2: 59.65,45.9 59.3,46.7 59.3,47.55 59.3,48.4
CSN2: C334.2 C335.2 L303.1 pad.@77.45,40.4 pad.@91.7,44.25 R306.2 R319.2 R332.1 | length 19.7
  TOP w0.2: pad.@91.7,44.25 92,44.25 92,44.2 92.4,43.8 92.9,43.8 R306.2@93,43.9
  BOTTOM w0.2: pad.@91.7,44.25 pad.@91.85,44.25
  BOTTOM w0.3: pad.@77.45,40.4 77.75,40.7 90.4,40.7 92.5,42.8 92.5,43.95 92.2,44.25 pad.@91.85,44.25
CSP1: C303.2 C304.2 C307.2 C308.2 C309.2 C312.2 C313.2 C314.2 FL301.1 pad.@57.2,43.55 pad.@57.2,44.55 pad.@61.25,44.3 Q302.5 R304.1 R324.2 | length 3.7
  TOP w0.2: R304.1@60.1,43.8 60.185,43.8 60.485,44.1 61.05,44.1 pad.@61.25,44.3
  BOTTOM w0.3: R324.2@60.85,43.075 60.85,43.9 pad.@61.25,44.3
  BOTTOM w0.8: pad.@57.2,43.55 pad.@57.2,44.55
  other v1: 54.4,44.55 55.3,44.55 53.5,45.45 54.4,45.45 55.3,45.45 56.2,45.45 53.5,46.35 54.4,46.35 55.3,46.35 56.2,46.35 57.1,46.35 53.5,47.25 54.4,47.25 55.3,47.25 56.2,47.25 57.1,47.25 53.5,48.15 54.4,48.15 55.3,48.15 56.2,48.15 57.1,48.15 53.5,49.05 54.4,49.05 55.3,49.05 56.2,49.05 57.1,49.05 53.5,49.95 54.4,49.95 55.3,49.95 56.2,49.95 57.1,49.95
CSP2: C319.1 Q305.1 Q305.2 Q305.5 Q305.6 Q305.7 R305.1 R330.1 TP308.1 | length 1.2
  TOP w0.2: R305.1@75.55,42.2 75.55,42.4 76,41.95 76,41.6
  other v2: 72.8,42.5 73.75,42.5 74.55,42.9
DH1: D303.C IC302.40 pad.@67.3,39.95 R302.2 | length 11.2
  BOTTOM w0.5: R302.2@65.24,46.65 66.5,46.65 67.05,46.1 ; pad.@67.3,39.95 68.25,40.9 68.25,43.2 67.35,44.1 67.35,45.8 67.05,46.1 ; D303.C@67.6,48 67.6,46.65 67.05,46.1
DH1_Q: Q303.3 R302.1 R303.1 R308.2 TP304.1
DH2: D305.C IC302.37 pad.@69.45,40.6 R315.2
DH2_Q: Q305.3 R311.2 R313.1 R315.1 TP309.1
DL1: D304.C IC302.2 pad.@66,38.55 R301.2
DL1_Q: Q304.3 R301.1 R307.1 R309.2 TP306.1
DL2: D306.C IC302.35 pad.@71.2,41 R316.2
DL2_Q: Q306.3 R312.2 R314.1 R316.1 TP311.1
GDRV: IC302.8 Q307.4 R320.2 TP314.1 | length 36.8
  Mid-Layer 2 w0.3: v1(65.5,34) 66.35,33.15 66.35,31.65 66,31.3 66,29.2 68.25,26.95 89.65,26.95 91.75,24.85 91.75,22.776 TP314.1@90.437,21.463
GND_A: C339.1 C340.1 C341.1 C342.2 C343.2 C345.2 C346.2 C349.1 C350.1 C351.1 C352.1 C353.1 C354.1 CN302.1T CN302.2T CN302.5 IC302.23 IC302.26 pad.@57.45,27.15 pad.@58.45,27.15 R329.2 R335.2 R337.2 R341.1 TP318.1 | length 8.7
  TOP w0.2: IC302.23@72.898,34.5 73.55,34.5 74.6,33.45
  BOTTOM w0.3: 76.75,31.6 C352.1@76.75,32.325 ; C353.1@79.27,37.981 82.046,37.981 ; R341.1@81.017,34.24 82.292,34.24 ; C354.1@81.024,36.972 81.899,36.972 ; R337.2@81.11,39.039 81.981,39.039
  other v1: 72.9,28.7 68.875,28.725 75.75,31.55 108.5,37.5 108.5,39 108.5,40.5 108.5,42 108.5,43.5
GND_P: C302.1 C303.1 C304.1 C306.1 C307.1 C308.1 C309.1 C311.1 C312.1 C313.1 C314.1 C316.1 C318.1 C319.2 C322.1 C323.1 C324.1 C325.1 C326.1 C327.1 C328.1 C329.1 C330.1 C331.1 C332.1 C333.1 C334.1 C335.1 C336.1 C337.1 C338.1 CN301.1T CN301.2 CN301.2T CN301.3T CN301.4T D301.A IC301.2 IC301.5 IC302.3 IC302.41 Q304.4 Q304.8 Q306.4 Q306.8 Q307.1 Q307.2 Q307.3 R309.1 R312.1 R319.1 R320.1 R329.1 TP307.1 TP312.1 TP316.1 TP331.1 TP332.1 TP333.1 TP334.1 | length 95.3
  TOP w0.2: IC302.3@67.002,37 IC302.41@68.3,37
  TOP w0.3: 87.9,21.503 R320.1@88.626,21.503 88.626,22.25
  TOP w1: 22.93,31.76 CN301.1T@22.93,30.535 CN301.2T@25.23,30.535 ; 22.93,48.34 CN301.4T@22.93,49.565 CN301.3T@25.23,49.565 ; 25.23,29.31 CN301.2T@25.23,30.535 ; 25.23,31.76 CN301.2T@25.23,30.535 ; 25.23,48.34 CN301.3T@25.23,49.565 ; 25.23,50.79 CN301.3T@25.23,49.565 ; 26.455,30.535 CN301.2T@25.23,30.535 ; 26.455,49.565 CN301.3T@25.23,49.565
  TOP w2.032: 33.75,43.3 CN301.2@36.3,43.3 ; 36.3,45.85 CN301.2@36.3,43.3 ; 38.85,43.3 CN301.2@36.3,43.3
  Mid-Layer 1 w1: 22.93,32.01 CN301.1T@22.93,30.535 CN301.2T@25.23,30.535 ; 22.93,48.057 CN301.4T@22.93,49.565 CN301.3T@25.23,49.565 ; 25.23,29.06 CN301.2T@25.23,30.535 ; 25.23,32.01 CN301.2T@25.23,30.535 ; 25.23,48.09 CN301.3T@25.23,49.565 ; 25.23,51.04 CN301.3T@25.23,49.565 ; 26.705,30.535 CN301.2T@25.23,30.535 ; 26.705,49.565 CN301.3T@25.23,49.565
  Mid-Layer 1 w2.032: 34,43.3 CN301.2@36.3,43.3 ; CN301.2@36.3,41.6 CN301.2@36.3,43.3 ; 36.3,45.6 CN301.2@36.3,43.3 ; 38.6,43.3 CN301.2@36.3,43.3
  Mid-Layer 2 w1: 22.93,32.01 CN301.1T@22.93,30.535 CN301.2T@25.23,30.535 ; 22.93,47.973 CN301.4T@22.93,49.565 CN301.3T@25.23,49.565 ; 25.23,29.06 CN301.2T@25.23,30.535 ; 25.23,32.01 CN301.2T@25.23,30.535 ; 25.23,47.973 CN301.3T@25.23,49.565 ; 25.23,51.04 CN301.3T@25.23,49.565 ; 26.705,30.535 CN301.2T@25.23,30.535 ; 26.705,49.565 CN301.3T@25.23,49.565
  Mid-Layer 2 w2.032: 34,43.3 CN301.2@36.3,43.3 ; CN301.2@36.3,41.65 CN301.2@36.3,43.3 ; 36.3,45.6 CN301.2@36.3,43.3 ; 38.6,43.3 CN301.2@36.3,43.3
  BOTTOM w0.4: 51.475,35.9 IC301.2@51.475,37.425
  BOTTOM w1: 22.93,31.76 CN301.1T@22.93,30.535 CN301.2T@25.23,30.535 ; 22.93,48.34 CN301.4T@22.93,49.565 CN301.3T@25.23,49.565 ; 25.23,29.31 CN301.2T@25.23,30.535 ; 25.23,31.76 CN301.2T@25.23,30.535 ; 25.23,48.34 CN301.3T@25.23,49.565 ; 25.23,50.79 CN301.3T@25.23,49.565 ; 26.455,30.535 CN301.2T@25.23,30.535 ; 26.455,49.565 CN301.3T@25.23,49.565
  BOTTOM w2.032: 34.15,43.3 CN301.2@36.3,43.3 36.3,45.45
  other v1: 27.6,21.35 29.6,21.35 31.6,21.35 33.05,21.35 34.8,21.35 38.8,21.35 40,21.35 61.75,21.5 64.25,21.5 66.75,21.5 69.25,21.5 71.75,21.5 74.25,21.5 76.75,21.5 77.8,21.8 78.7,21.8 79.6,21.8 80.5,21.8 81.4,21.8 82.3,21.8 83.2,21.8 84.1,21.8 85,21.8 85.9,21.8 86.8,21.8 87.7,21.8 77.8,22.7 78.7,22.7 79.6,22.7 80.5,22.7 81.4,22.7 82.3,22.7 83.2,22.7 84.1,22.7 85,22.7 85.9,22.7 86.8,22.7 87.7,22.7 77.8,23.6 78.7,23.6 79.6,23.6 80.5,23.6 81.4,23.6 82.3,23.6 83.2,23.6 84.1,23.6 85,23.6 85.9,23.6 86.8,23.6 87.7,23.6 27.6,23.85 29.6,23.85 77.8,24.5 78.7,24.5 79.6,24.5 80.5,24.5 81.4,24.5 82.3,24.5 83.2,24.5 84.1,24.5 85,24.5 85.9,24.5 86.8,24.5 87.7,24.5 77.8,25.4 78.7,25.4 79.6,25.4 80.5,25.4 81.4,25.4 82.3,25.4 83.2,25.4 84.1,25.4 85,25.4 85.9,25.4 86.8,25.4 87.7,25.4 26.4,27.95 28.9,27.95 80.5,29 81.4,29 82.3,29 83.2,29 84.1,29 85,29 88.5,29 89.4,29 90.3,29 91.2,29 92.1,29 93,29 55.25,32.25 56.15,32.25 57.05,32.25 57.95,32.25 21.4,32.95 23.9,32.95 26.4,32.95 28.9,32.95 54.35,33.15 55.25,33.15 56.15,33.15 57.05,33.15 57.95,33.15 54.35,34.05 55.25,34.05 56.15,34.05 57.05,34.05 57.95,34.05 54.35,34.95 55.25,34.95 56.15,34.95 57.05,34.95 57.95,34.95 21.4,35.45 23.9,35.45 26.4,35.45 28.9,35.45 54.35,35.85 55.25,35.85 56.15,35.85 57.05,35.85 57.95,35.85 54.35,36.75 55.25,36.75 56.15,36.75 57.05,36.75 57.95,36.75 65.25,37.25 64.5,37.7 21.4,37.95 23.9,37.95 26.4,37.95 28.9,37.95 21.4,40.45 23.9,40.45 26.4,40.45 28.9,40.45 31.4,40.45 21.4,42.95 23.9,42.95 26.4,42.95 28.9,42.95 31.4,42.95 21.4,45.45 23.9,45.45 26.4,45.45 28.9,45.45 31.4,45.45 33.9,45.45 81.25,46 82.15,46 83.05,46 83.95,46 84.85,46 85.75,46 86.65,46 87.55,46 38.9,46.3 81.25,46.9 82.15,46.9 83.05,46.9 83.95,46.9 84.85,46.9 85.75,46.9 86.65,46.9 87.55,46.9 39.9,47.1 81.25,47.8 82.15,47.8 83.05,47.8 83.95,47.8 84.85,47.8 85.75,47.8 86.65,47.8 87.55,47.8 21.4,47.95 23.9,47.95 26.4,47.95 28.9,47.95 31.4,47.95 33.9,47.95 38.9,47.95 40.7,47.95 81.25,48.7 82.15,48.7 83.05,48.7 83.95,48.7 84.85,48.7 85.75,48.7 86.65,48.7 87.55,48.7 41.55,48.75 38.9,49.55 40.7,49.55 42.3,49.55 81.25,49.6 82.15,49.6 83.05,49.6 83.95,49.6 84.85,49.6 85.75,49.6 86.65,49.6 87.55,49.6 43.2,50.35 31.4,51.1 33.9,51.1 36.4,51.1 38.9,51.1 41.4,51.1 43.9,51.1 31.4,53.6 33.9,53.6 36.4,53.6 38.9,53.6 41.4,53.6 81.25,55.8 82.15,55.8 83.05,55.8 83.95,55.8 84.85,55.8 85.75,55.8 86.65,55.8 87.55,55.8 88.45,55.8 91.5,55.8 92.4,55.8 93.3,55.8 94.2,55.8 95.1,55.8 96,55.8 96.9,55.8 97.8,55.8 98.7,55.8 43.9,56.1 81.25,56.7 82.15,56.7 83.05,56.7 83.95,56.7 84.85,56.7 85.75,56.7 86.65,56.7 87.55,56.7 88.45,56.7 91.5,56.7 92.4,56.7 93.3,56.7 94.2,56.7 95.1,56.7 96,56.7 96.9,56.7 97.8,56.7 98.7,56.7 81.25,57.6 82.15,57.6 83.05,57.6 83.95,57.6 84.85,57.6 85.75,57.6 86.65,57.6 87.55,57.6 88.45,57.6 91.5,57.6 92.4,57.6 93.3,57.6 94.2,57.6 95.1,57.6 96,57.6 96.9,57.6 97.8,57.6 98.7,57.6 81.25,58.5 82.15,58.5 83.05,58.5 83.95,58.5 84.85,58.5 85.75,58.5 86.65,58.5 87.55,58.5 88.45,58.5 91.5,58.5 92.4,58.5 93.3,58.5 94.2,58.5 95.1,58.5 96,58.5 96.9,58.5 97.8,58.5 98.7,58.5 53.8,58.55 31.4,58.6 33.9,58.6 36.4,58.6 38.9,58.6 41.4,58.6 43.9,58.6 46.4,58.6 48.9,58.6 51.4,58.6
  other v2: 68.3,34.1 71.6,34.1 68.3,37.4 71.6,37.4 63,38.45 63.85,38.45 63,39.35 63.85,39.35 63,40.25 63.85,40.25
HVCC1: C350.2 CN303.7 IC302.25 | length 37.1
  TOP w0.3: CN303.7@100.735,43 100.835,42.9 v1(103.45,42.9)
  Mid-Layer 2 w0.3: v1(74.8,35.1) 95.65,35.1 v1(103.45,42.9)
  BOTTOM w0.3: v1@103.45,42.864 C350.2@104.667,42.864 104.631,42.9 v1(103.45,42.9)
HVCC2: C349.2 CN303.6 IC302.24 | length 35.3
  TOP w0.3: CN303.6@100.735,41 v1(103.45,41)
  Mid-Layer 2 w0.3: v1(74.8,34.2) 75.939,34.2 76.289,34.55 95.856,34.55 102.306,41 v1(103.45,41)
  BOTTOM w0.3: v1(103.45,41) 104.572,41 C349.2@104.594,41.022
HVDM: CN303.5 IC302.21 | length 35.1
  TOP w0.3: CN303.5@100.735,39 v1(103.45,39)
  Mid-Layer 2 w0.3: v1(73.65,32.85) 74.45,32.85 74.52,32.92 97.37,32.92 v1(103.45,39)
HVDP: CN303.4 IC302.22 | length 33.5
  TOP w0.3: CN303.4@100.735,37 v1(103.45,37)
  Mid-Layer 2 w0.3: v1(74.7,32.1) 74.925,32.325 97.482,32.325 102.157,37 v1(103.45,37)
HVEN: IC302.6 pad.@65.5,35.35 R334.2 R335.1 | length 8
  BOTTOM w0.3: pad.@65.5,35.35 67.6,33.25 68.6,33.25 70.425,31.425 R334.2@70.425,31 70.425,30.1 R335.1@70.5,30.025
LX1: C317.2 IC302.39 L302.1 Q303.4 Q303.8 Q304.1 Q304.2 Q304.5 Q304.6 Q304.7 R308.1 TP305.1 | length 8.2
  Mid-Layer 1 w0.5: TP305.1@62.85,47.65 65.25,47.65 67.4,45.5 67.4,42.85 v1(67.3,42.85)
  other v2: 66.4,43.3 65.2,45.1 66.25,45.1 65.75,45.7
LX2: C320.2 IC302.38 L302.2 Q305.4 Q305.8 Q306.1 Q306.2 Q306.5 Q306.6 Q306.7 R311.1 TP310.1 | length 5.9
  Mid-Layer 1 w0.5: v1(69.15,42.8) 69.15,45.45 70.3,46.6 TP310.1@71.9,46.6
  other v2: 76.1,48.8 76.95,49.15 77.8,49.15 78.65,49.15
OUT: C323.2 C324.2 C325.2 C326.2 C327.2 C328.2 C329.2 C330.2 C331.2 C332.2 C333.2 pad.@76.75,41.15 pad.@91.7,43.2 R305.2 R306.1 R331.1 | length 18.4
  TOP w0.2: pad.@91.7,43.2 92.15,43.2 92.294,43.344 92.663,43.344 93.206,42.8 R306.1@94,42.8
  BOTTOM w0.3: pad.@76.75,41.15 76.9,41.3 89.8,41.3 pad.@91.7,43.2
SCL: CN302.3 pad.@52.8,26.55 R322.2 R327.2 | length 9.6
  TOP w0.5: pad.@52.8,26.55 53.121,26.871 CN302.3@53.121,29.217
  BOTTOM w0.3: R322.2@52.8,27.575 pad.@52.8,26.55 54.85,24.5 R327.2@57.725,24.5
SDA: CN302.4 pad.@54.6,26.55 R321.2 R328.2 | length 7.5
  TOP w0.5: pad.@54.6,26.55 55.121,27.071 CN302.4@55.121,29.217
  BOTTOM w0.3: R321.2@54.6,27.575 pad.@54.6,26.55 55.45,25.7 R328.2@57.825,25.7
SHLD_SNS: C338.2 CN303.1 CN303.1T CN303.2 CN303.2T CN303.3 IC302.7 Q307.5 TP315.1 | length 38.3
  TOP w0.2: v1(64.45,34) 65.15,34.7 66.2,34.7 66.5,35 IC302.7@67.002,35
  Mid-Layer 2 w0.3: v1(64.45,34) 64.45,34.45 64.7,34.7 66.15,34.7 67.8,33.05 67.8,28.5 68.7,27.6 89.85,27.6 92.55,24.9
  other v1: 92.95,21.45 94.6,21.45 96,21.45 97.1,21.45 98.5,21.5 92.55,22.25 93.4,22.25 94.25,22.25 95.1,22.25 99.5,22.25 100.5,23.25 101.5,24.25 92.55,25.65 93.4,25.65 94.25,25.65 95.1,25.65 95.25,27.25 96.25,27.25 97.25,27.25 98.25,28 99,28.75 103.45,30.55 104.35,30.55 105.25,30.55 106.15,30.55 103.45,31.45 104.35,31.45 105.25,31.45 106.15,31.45 103.45,32.35 104.35,32.35 105.25,32.35 106.15,32.35 103.45,33.25 104.35,33.25 105.25,33.25 106.15,33.25
SIG214: D309.A Q301.1 Q301.2 Q301.3 Q302.1 Q302.2 Q302.3
SIG247: C318.2 D301.C IC301.6 R310.1
SIG310: C351.2 IC302.27 pad.@73.9,36.6 R333.2 | length 4.1
  BOTTOM w0.3: pad.@73.9,36.6 75.062,36.6 75.722,35.941 75.722,35.029 75.734,35.041 R333.2@76.784,35.041
SIG311: C352.2 R333.1 | length 0.8
  BOTTOM w0.3: C352.2@76.75,33.175 R333.1@76.75,34.025
SIG313: C354.2 R336.1 R338.2 | length 1.9
  BOTTOM w0.3: R338.2@79.113,36.027 79.254,36.168 R336.1@79.254,36.97 80.173,36.97 C354.2@80.174,36.972
SIG316: C355.1 R340.1 R341.2 | length 1.9
  BOTTOM w0.3: R340.1@79.275,34.251 80.156,34.251 R341.2@80.167,34.24 80.167,35.042 C355.1@80.306,35.181
SIG317: C355.2 R338.1
SIG318: C353.2 IC302.30 pad.@73.85,38.55 R336.2 R340.2 | length 8.7
  BOTTOM w0.3: pad.@73.85,38.55 74.2,38.2 76.6,38.2 76.819,37.981 C353.2@78.42,37.981 R336.2@78.42,36.853 ; R336.2@78.404,36.97 78.404,34.273 R340.2@78.425,34.251
SIG319: C347.1 C348.2 IC302.32 R331.2 | length 1.9
  TOP w0.2: IC302.32@71.7,38.948 71.7,39 72.875,40.175 C347.1@73.1,40.175
SIG324: C348.1 IC302.31 R332.2 | length 2.5
  TOP w0.2: IC302.31@72.2,38.948 72.398,38.948 72.725,39.275 C348.1@74.575,39.275
SIG328: C347.2 IC302.33 R330.2 | length 3.1
  TOP w0.2: IC302.33@71.2,38.8 71.2,39.1 73.113,41.013 C347.2@73.175,40.95
SIG335: C344.1 IC302.5 pad.@64.5,35.75 R324.1 | length 8.5
  BOTTOM w0.2: 64.05,35.75 pad.@64.5,35.75
  BOTTOM w0.3: R324.1@60.85,42.225 60.85,41.175 C344.1@60.875,41.15 60.875,38.475 63.6,35.75 64.05,35.75
SIG337: C344.2 IC302.4 pad.@64.5,36.7 R323.1 | length 7.4
  BOTTOM w0.3: R323.1@61.85,42.225 61.84,42.235 61.84,42.18 61.725,42.065 C344.2@61.725,41.15 61.725,38.375 63.4,36.7 pad.@64.5,36.7
SIG341: IC302.10 TP325.1
SIG344: IC302.19 R326.1 TP320.1
SIG345: IC302.18 R326.2 TP321.1
SIG346: C345.1 IC302.13
SIG347: C346.1 IC302.17
SIG349: IC302.14 TP326.1
SIG350: IC302.15 TP327.1
SIG369: IC302.11 pad.@66.65,30.35 R327.1 TP323.1 | length 10.4
  BOTTOM w0.3: R327.1@58.675,24.5 59.7,24.5 TP323.1@59.75,24.45 60.25,24.95 61.05,24.95 65.503,29.403 65.703,29.403 pad.@66.65,30.35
